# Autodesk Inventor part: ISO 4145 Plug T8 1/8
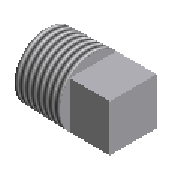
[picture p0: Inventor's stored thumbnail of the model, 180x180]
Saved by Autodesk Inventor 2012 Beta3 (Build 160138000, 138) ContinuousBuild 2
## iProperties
IsCustomPart: 0
Created: 2010-02
Part Number: ISO 4145 Plug T8 1/8
Material: Non-Alloy Steel
Description: ISO 4145 Non-alloy steel fittings threaded to ISO 7/1 - Plug T8
Document SubType Name: Modeling
Standard: ISO 4145
Designer: Thom Tremblay
Standard Revision: Second edition 1986-07-15
Standards Organization: ISO
Language: en-US
Size Designation: 1/8
Categories: <MemberInstance><Categories><Category DisplayName="Tube &amp; Pipe" InternalName="4347fa0f-2144-441d-94cd-e3e15c92b736" Mnemonic="TUBEANDPIPE"><CategoryParamete
Density: 1 g/cm^3
NAME: PIPING: ISO 4145 Plug T8
DATA: <meta><inlinegroups number="0" deflen="0"></inlinegroups><connections number="1"></connections><angles></angles></meta>
Author: Thom Tremblay
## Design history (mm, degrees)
sketch "Sketch2"
  geometry: C1 r 4.74 at (0, 0) reference; C2 r 4.3 at (0, 0)
  constraints: 1 centre point, 1 coincident, 1 concentric
  dimensions: "d2" = 8.6 diameter of C2 (= d3)
revolve "Revolve1" sketch "Sketch2" stored, may be unused: angle "d4" = 90 deg
sketch "Sketch3"
  geometry: L1 (-3.5, -3.5)-(3.5, -3.5); L2 (3.5, -3.5)-(3.5, 3.5); L3 (3.5, 3.5)-(-3.5, 3.5); L4 (-3.5, 3.5)-(-3.5, -3.5); L5 (-3.5, -3.5)-(3.5, 3.5); L6 (3.5, -3.5)-(-3.5, 3.5); C1 r 4.959 at (0, 0) reference; 1 further point
  constraints: 12 end point, 2 parallel, 2 perpendicular, 1 coincident, 1 horizontal, 1 midpoint
  dimensions: "d7" = 7 distance of L2.end L3.end (= S1)
extrude "Extrude1" cut sketch "Sketch3" distance "d5" = 6 (= -n + L - k); taper "d6" = 0 deg
thread "Thread1" dims "d8" = 10, "d9" = 0
extrude "Extrude2" join sketch "Sketch3" distance "d10" = 6 (= n); taper "d11" = 0 deg
workaxis "Work Axis1"
workpoint "Work Point1"
workaxis "Work Axis2"
workpoint "Work Point2"
body "Solid1"
sketch "Sketch1"
  geometry: L1 (0, 0)-(-7, 0); L2 (0, 4.74)-(0, 0); L3 (0, 4.74)-(-7, 4.959); L4 (-7, 4.959)-(-7, 0); L5 (-3.97, 4.864)-(-3.97, 0)
  constraints: 10 end point, 2 point on line, 1 horizontal, 1 perpendicular, 1 vertical
  dimensions: "d0" = 7 distance between parallel lines of L2 L4 (= L - n); "d1" = 1.78991 deg angle of L1 L3; "d12" = 3.97 distance between parallel lines of L2 L5 (= a); "d13" = 9.728 diameter of L5.start L1 (= MjD)
other parameters: "L" = 13 [user parameter; used in 2 equation terms], "n" = 6 [user parameter; used in 3 equation terms], "d3" = 8.6 [user parameter; used in 1 equation term], "k" = 1 [user parameter; used in 1 equation term], "S1" = 7 [user parameter; used in 1 equation term], "a" = 3.97 [user parameter; used in 1 equation term], "MjD" = 9.728 [user parameter; used in 1 equation term], "a1" = 2.5 [user parameter], "Size_Designation" = 1.25 [user parameter]
